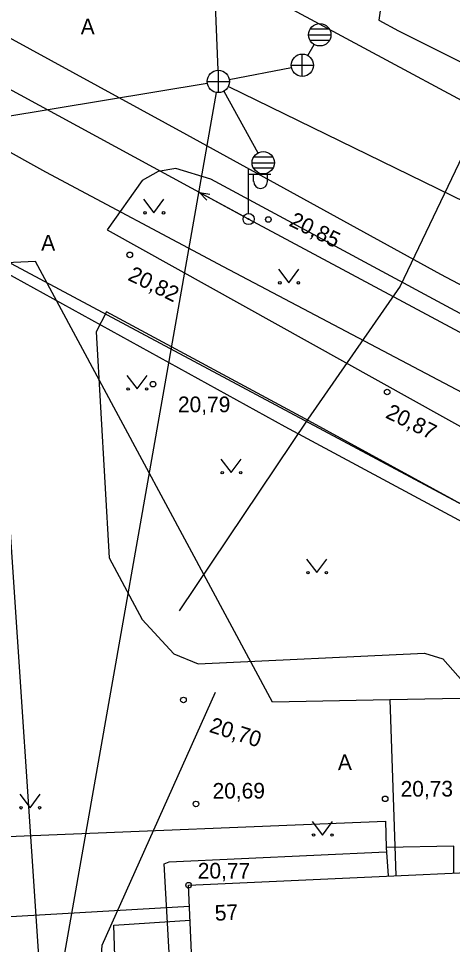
# Model space of a CAD drawing. Extents: x 714038 to 714279, y 6589845 to 6590041.
# Drawn here: x 714195.16 to 714214.57, y 6589892.78 to 6589934.18 of the extents above; entities that cross this region are included whole.
import ezdxf

# ---------------------------------------------------------------- set-up
doc = ezdxf.new("R2010")
doc.units = 0
for name, color, linetype in [('HALJASTUS', 7, 'Continuous'), ('HOONE', 7, 'Continuous'), ('HOONEDET', 7, 'Continuous'), ('KKAEV', 7, 'Continuous'), ('KORGUS', 7, 'Continuous'), ('KPKAABEL', 7, 'Continuous'), ('MPKAABEL', 7, 'Continuous'), ('MPOHULIIN', 7, 'Continuous'), ('POST', 7, 'Continuous'), ('SITRASS', 7, 'Continuous'), ('SKKAEV', 7, 'Continuous'), ('SKTRASS', 7, 'Continuous'), ('TEE', 7, 'Continuous'), ('TTRASS', 7, 'Continuous'), ('VTRASS', 7, 'Continuous'), ('Слой 1', 7, 'Continuous')]:
    doc.layers.add(name, color=color, linetype=linetype)

msp = doc.modelspace()

# ---------------------------------------------------------------- linework, layer by layer
at = {"layer": 'HALJASTUS'}
for p, q in [((714200.759, 6589926.096), (714201.222, 6589925.489)), ((714201.222, 6589925.489), (714201.668, 6589926.096)), ((714206.789, 6589922.967), (714207.253, 6589922.36)), ((714207.253, 6589922.36), (714207.698, 6589922.967)), ((714200.002, 6589918.222), (714200.466, 6589917.616)), ((714200.466, 6589917.616), (714200.911, 6589918.222)), ((714204.212, 6589914.48), (714204.675, 6589913.873)), ((714204.675, 6589913.873), (714205.121, 6589914.48)), ((714208.043, 6589910.011), (714208.507, 6589909.405)), ((714208.507, 6589909.405), (714208.952, 6589910.011)), ((714195.217, 6589899.497), (714195.68, 6589898.89)), ((714195.68, 6589898.89), (714196.126, 6589899.497)), ((714208.297, 6589898.277), (714208.76, 6589897.67)), ((714208.76, 6589897.67), (714209.206, 6589898.277))]:
    msp.add_line(p, q, dxfattribs=at)
for centre in [(714200.821, 6589925.489), (714201.65, 6589925.489), (714206.852, 6589922.36), (714207.68, 6589922.36), (714200.065, 6589917.616), (714200.894, 6589917.616), (714204.274, 6589913.873), (714205.103, 6589913.873), (714208.106, 6589909.405), (714208.934, 6589909.405), (714195.279, 6589898.89), (714196.108, 6589898.89), (714208.359, 6589897.67), (714209.188, 6589897.67)]:
    msp.add_circle(centre, 0.055, dxfattribs=at)
at = {"layer": 'HOONE'}
for points in [[(714037.81, 6590017.576), (714059.08, 6590006.51), (714072.38, 6589999.69), (714082.14, 6589994.37), (714104.85, 6589981.96), (714150.21, 6589957.43), (714183.55, 6589939.45), (714202.68, 6589928.99), (714214.04, 6589922.75), (714222.92, 6589918.06), (714237.47, 6589910.29), (714252.27, 6589902.23), (714256.602, 6589899.815), (714258.577, 6589898.715), (714261.69, 6589896.98)], [(714232.775, 6589897.266), (714232.58, 6589904.16), (714223.55, 6589903.94), (714211.77, 6589903.72), (714206.52, 6589903.61), (714195.92, 6589923.31), (714175.53, 6589922.39), (714175.7, 6589917.845), (714175.811, 6589914.882), (714176.08, 6589907.69)], [(714211.77, 6589903.72), (714212.04, 6589895.86)], [(714224.4, 6589896.416), (714231.818, 6589896.708), (714231.798, 6589897.222), (714234.283, 6589897.334), (714234.304, 6589896.805), (714243.421, 6589897.164), (714244.031, 6589886.542), (714224.36, 6589885.65), (714203.25, 6589884.69), (714202.77, 6589895.43), (714224.4, 6589896.416)]]:
    msp.add_lwpolyline(points, dxfattribs=at)
at = {"layer": 'HOONEDET'}
for points in [[(714214.63, 6589895.98), (714214.63, 6589897.17), (714211.6, 6589897.12), (714211.69, 6589895.84)], [(714209.04, 6589884.09), (714202.38, 6589883.92), (714201.68, 6589896.39), (714201.9, 6589896.47), (714211.61, 6589896.92)]]:
    msp.add_lwpolyline(points, dxfattribs=at)
at = {"layer": 'KKAEV'}
for p, q in [((714207.856, 6589931.587), (714207.856, 6589932.587)), ((714207.356, 6589932.087), (714208.356, 6589932.087)), ((714204.101, 6589930.863), (714204.101, 6589931.863)), ((714203.601, 6589931.363), (714204.601, 6589931.363))]:
    msp.add_line(p, q, dxfattribs=at)
for centre in [(714207.856, 6589932.087), (714204.101, 6589931.363)]:
    msp.add_circle(centre, 0.5, dxfattribs=at)
at = {"layer": 'KORGUS'}
for centre in [(714206.34, 6589925.19), (714200.14, 6589923.61), (714201.18, 6589917.83), (714211.65, 6589917.48), (714202.54, 6589903.71), (714211.56, 6589899.29), (714203.1, 6589899.06), (714202.77, 6589895.43)]:
    msp.add_circle(centre, 0.125, dxfattribs=at)
at = {"layer": 'KPKAABEL'}
for points in [[(714278.95, 6590013.083), (714274.696, 6590002.154), (714268.806, 6589986.746), (714264.689, 6589977.209), (714260.118, 6589965.851), (714258.032, 6589961.24), (714253.05, 6589949.372), (714248.466, 6589938.096), (714247.531, 6589934.989), (714246.389, 6589934.367), (714239.483, 6589937.254), (714226.492, 6589940.819), (714222.669, 6589940.979), (714220.982, 6589941.049), (714220.257, 6589940.365), (714218.76, 6589936.611), (714215.836, 6589929.757), (714212.225, 6589922.206), (714208.098, 6589916.26), (714202.344, 6589907.69)], [(714195.617, 6589845.18), (714198.91, 6589892.74), (714203.97, 6589904.053)]]:
    msp.add_lwpolyline(points, dxfattribs=at)
at = {"layer": 'MPKAABEL'}
for points in [[(714215.066, 6589943.967), (714214.846, 6589942.32), (714213.494, 6589938.395), (714212.085, 6589935.688), (714211.383, 6589934.84), (714211.278, 6589934.105), (714212.162, 6589933.623), (714233.552, 6589922.923), (714249.701, 6589913.675), (714250.295, 6589914.005), (714250.521, 6589914.785), (714251.05, 6589918.335), (714251.513, 6589923.366), (714251.481, 6589924.441), (714250.114, 6589927.476), (714252.56, 6589933.122), (714254.403, 6589936.762), (714260.237, 6589952.896), (714261.787, 6589959.195)], [(714205.454, 6589925.211), (714176.708, 6589940.841)], [(714231.9, 6589911.052), (714205.454, 6589925.211)], [(714200.004, 6589845.18), (714200.89, 6589848.6), (714199.42, 6589893.64), (714202.84, 6589893.86)]]:
    msp.add_lwpolyline(points, dxfattribs=at)
at = {"layer": 'MPOHULIIN'}
for p, q in [((714203.257, 6589926.404), (714203.582, 6589926.057)), ((714203.257, 6589926.404), (714203.725, 6589926.319)), ((714205.234, 6589925.33), (714203.257, 6589926.404))]:
    msp.add_line(p, q, dxfattribs=at)
at = {"layer": 'POST'}
for p, q in [((714205.454, 6589925.461), (714205.454, 6589927.461)), ((714205.454, 6589927.211), (714206.454, 6589927.211)), ((714205.68, 6589926.89), (714205.68, 6589927.211)), ((714206.293, 6589926.89), (714206.293, 6589927.211))]:
    msp.add_line(p, q, dxfattribs=at)
for radius in [0.25, 0.0234]:
    msp.add_circle((714205.454, 6589925.211), radius, dxfattribs=at)
msp.add_arc((714205.987, 6589926.89), 0.306, 180, 0, dxfattribs=at)
at = {"layer": 'SITRASS'}
msp.add_lwpolyline([(714227.213, 6589905.211), (714223.017, 6589907.372), (714207.091, 6589915.92), (714188.911, 6589925.93), (714174.372, 6589933.714)], dxfattribs=at)
at = {"layer": 'SKKAEV'}
for p, q in [((714209.066, 6589933.699), (714208.206, 6589933.699)), ((714208.136, 6589933.449), (714209.136, 6589933.449)), ((714209.066, 6589933.199), (714208.206, 6589933.199)), ((714206.54, 6589927.98), (714205.68, 6589927.98)), ((714205.61, 6589927.73), (714206.61, 6589927.73)), ((714206.54, 6589927.48), (714205.68, 6589927.48))]:
    msp.add_line(p, q, dxfattribs=at)
for centre in [(714208.636, 6589933.449), (714206.11, 6589927.73)]:
    msp.add_circle(centre, 0.5, dxfattribs=at)
at = {"layer": 'SKTRASS'}
for points in [[(714203.819, 6589938.089), (714204.081, 6589931.863)], [(714208.104, 6589932.521), (714208.387, 6589933.016)], [(714204.592, 6589931.458), (714207.365, 6589931.992)], [(714168.503, 6589925.288), (714178.38, 6589927.11), (714203.608, 6589931.282)], [(714204.551, 6589931.144), (714222.61, 6589922.33), (714241.548, 6589913.176), (714241.548, 6589913.176)], [(714196.31, 6589887.14), (714204.017, 6589930.87)], [(714204.343, 6589930.926), (714205.868, 6589928.168)]]:
    msp.add_lwpolyline(points, dxfattribs=at)
at = {"layer": 'TEE'}
for points in [[(714263.275, 6589906.612), (714262.481, 6589906.156), (714261.368, 6589906.05), (714260.213, 6589906.315), (714240.788, 6589916.652), (714217.995, 6589928.881), (714199.241, 6589938.974), (714197.452, 6589940.713), (714195.768, 6589942.431), (714184.455, 6589948.554)], [(714260.872, 6589896.331), (714241.905, 6589906.497), (714241.183, 6589906.16), (714240.441, 6589906.543), (714240.721, 6589907.111), (714236.852, 6589909.204), (714214.108, 6589921.428), (714203.766, 6589926.993), (714202.202, 6589927.469), (714201.413, 6589927.345), (714200.699, 6589926.934), (714199.125, 6589924.726), (714220.312, 6589912.945), (714241.895, 6589901.346), (714256.945, 6589893.296)], [(714193.769, 6589920.826), (714194.239, 6589910.779), (714194.69, 6589897.613), (714211.578, 6589898.295), (714211.6, 6589897.12)], [(714228.18, 6589905.231), (714207.986, 6589916.277), (714199.093, 6589921.068), (714198.639, 6589920.168), (714199.213, 6589910.066), (714200.697, 6589907.311), (714202.103, 6589905.776), (714203.2, 6589905.324), (714213.313, 6589905.801), (714214.147, 6589905.548), (714216.152, 6589903.272), (714217.072, 6589902.693), (714227.265, 6589902.742), (714228.249, 6589902.983)]]:
    msp.add_lwpolyline(points, dxfattribs=at)
at = {"layer": 'TTRASS'}
msp.add_lwpolyline([(714202.81, 6589894.48), (714189.63, 6589893.72)], dxfattribs=at)
at = {"layer": 'VTRASS'}
msp.add_lwpolyline([(714219.771, 6589914.924), (714218.336, 6589915.691), (714204.329, 6589923.078), (714196.383, 6589927.305), (714185.655, 6589933.263), (714178.705, 6589937.104), (714170.033, 6589941.737), (714162.674, 6589944.874), (714154.781, 6589949.135), (714153.798, 6589949.498)], dxfattribs=at)
at = {"layer": 'Слой 1'}
msp.add_lwpolyline([(714246.86, 6589895.42), (714247.69, 6589881.35), (714196.91, 6589879.78), (714193.95, 6589923.69)], close=True, dxfattribs=at)

# ---------------------------------------------------------------- texts
at = {"layer": 'HOONE'}
msp.add_text('57', height=0.7, rotation=2.6207, dxfattribs=at).set_placement((714203.958, 6589893.835))
at = {"layer": 'KORGUS'}
for s, rotation, p in [('20,85', 334.0139, (714207.224, 6589924.929)), ('20,82', 334.0139, (714200.012, 6589922.504)), ('20,87', 334.0139, (714211.534, 6589916.349)), ('20,70', 342.4417, (714203.654, 6589902.289)), ('20,73', 0.2279, (714212.253, 6589899.386)), ('20,69', 0.2279, (714203.844, 6589899.296))]:
    msp.add_text(s, height=0.7, rotation=rotation, dxfattribs=at).set_placement(p)
for s, p in [('20,79', (714202.294, 6589916.575)), ('20,77', (714203.181, 6589895.725))]:
    msp.add_text(s, height=0.7, dxfattribs=at).set_placement(p)
at = {"layer": 'TEE'}
for p in [(714197.947, 6589933.469), (714196.178, 6589923.805)]:
    msp.add_text('A', height=0.7, dxfattribs=at).set_placement(p)
msp.add_text('A', height=0.7, rotation=1.2086, dxfattribs=at).set_placement((714209.45, 6589900.571))

doc.saveas('drawing.dxf')
